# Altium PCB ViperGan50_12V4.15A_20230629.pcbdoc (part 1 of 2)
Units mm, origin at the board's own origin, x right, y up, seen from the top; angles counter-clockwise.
Board outline 450.19 x 402.29 mm, 2 copper layers (Top Layer, Bottom Layer); 71 components, 42 nets, 203 pads, 97 vias.
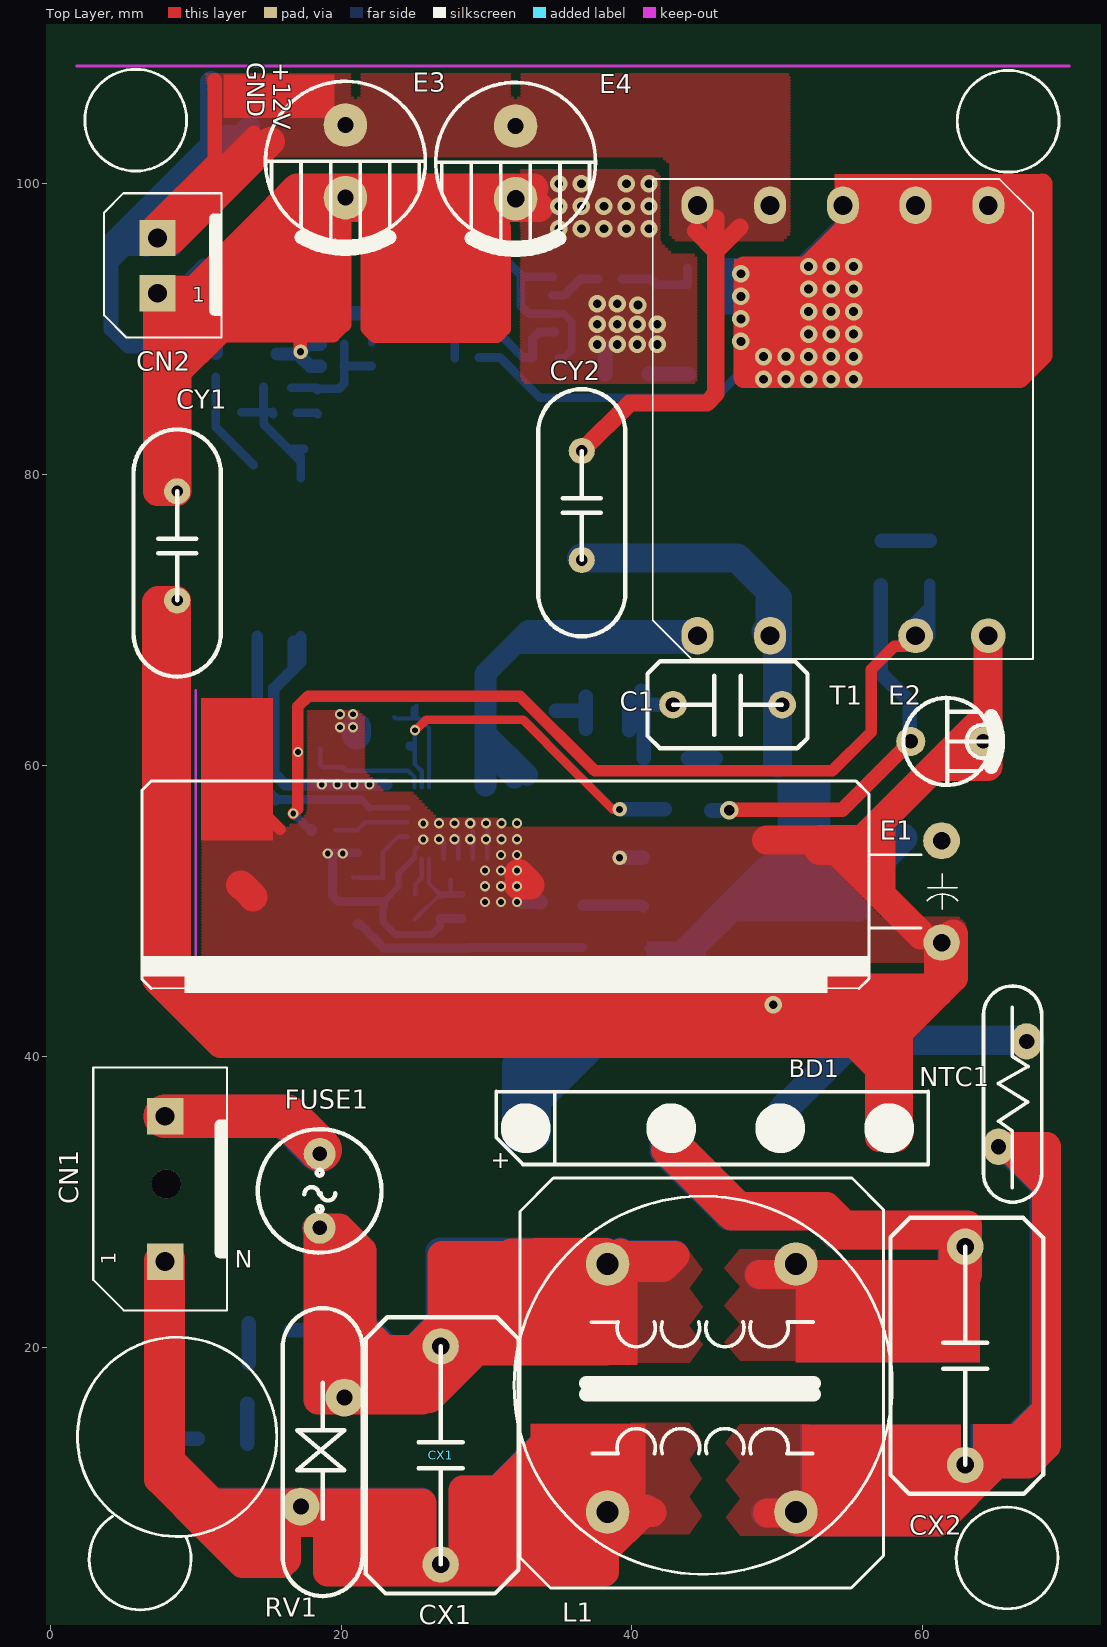
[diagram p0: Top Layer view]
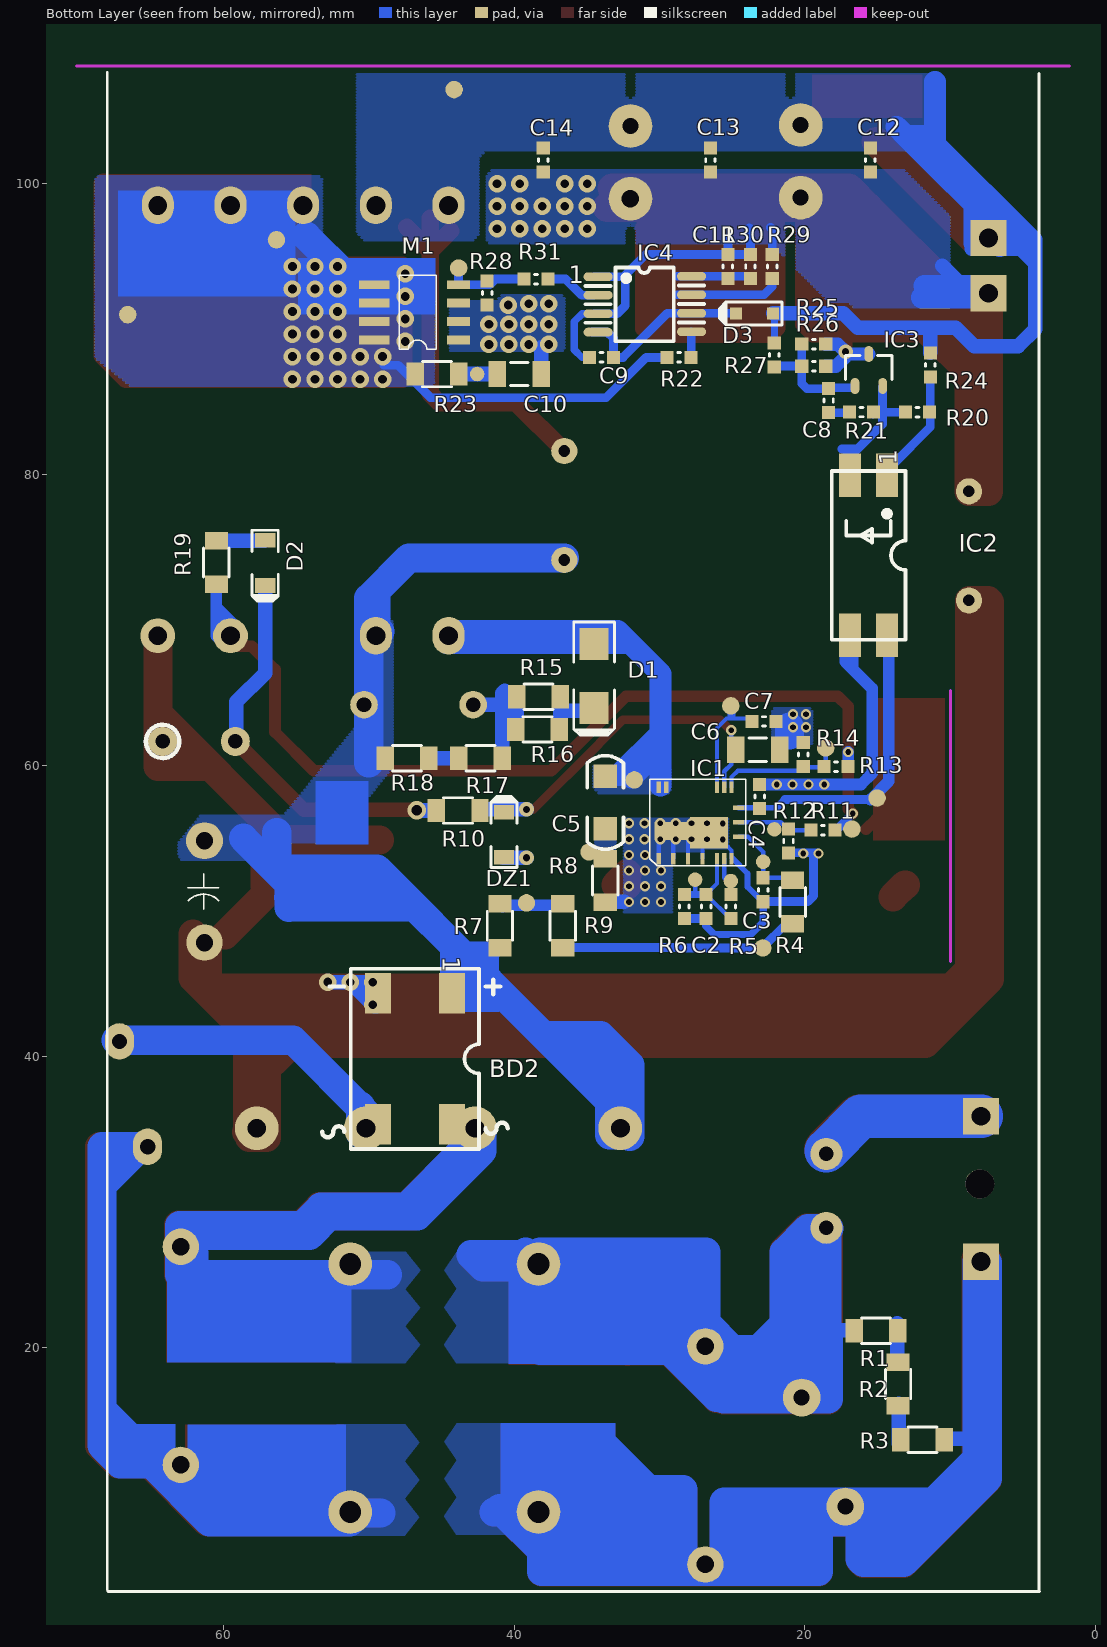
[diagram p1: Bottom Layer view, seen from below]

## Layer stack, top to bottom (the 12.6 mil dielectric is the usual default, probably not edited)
Top Solder: solder mask 0.0102, Solder Resist, Dk 3.5
Top Layer: signal copper 0.0356
Dielectric1: dielectric 0.32, FR-4, Dk 4.8
Bottom Layer: signal copper 0.0356
Bottom Solder: solder mask 0.0102, Solder Resist, Dk 3.5

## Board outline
-290.477,269.395 159.715,269.395 159.715,-132.89 159.009,-132.184 -290.477,-132.184

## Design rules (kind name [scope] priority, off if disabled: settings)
Clearance [All] p1: gap=0.2 ignorepadtopadclearanceinfootprint=FALSE except(0: Arc-Hole Track-Hole SMDPad-Hole THPad-Hole Via-Hole Fill-Hole Poly-Hole Region-Hole Text-Hole)
ComponentClearance [All] p1: gap=0 collisioncheckmode=3 verticalgap=0 showdistances=FALSE
FabricationTestPointUsage TestPointUsage [All] p1: valid=0 allowmultiple=FALSE
FabricationTestpoint Testpoint [(IsPad And (OnTopLayer Or OnBottomLayer))] p1: side=3 testpointundercomponent=TRUE minsize=1.016 maxsize=2.54 preferedsize=1.524 minholesize=0 maxholesize=1.016 preferedholesize=0.813 testpointgrid=0.025 allowsidetop=TRUE allowsidebottom=TRUE usegrid=TRUE gridtolerance=0
Height [All] p1: minheight=0 maxheight=32.4 prefheight=32.4
PlaneConnect [All] p1: planeconnectstyle=Direct reliefexpansion=0.508 reliefentries=4 reliefconductorwidth=0.254 reliefairgap=0.254
PolygonConnect [All] p1: connectstyle=Direct reliefconductorwidth=0.254 reliefentries=4 polygonreliefangle="90 Angle" airgapwidth=0.254
RoutingVias [All] p1: holewidth=0.711 width=1.27 viastyle="Through Hole" minholewidth=0.711 minwidth=1.27 maxholewidth=0.711 maxwidth=1.27
SilkToSolderMaskClearance SilkscreenOverComponentPads [IsPad] p1: minsilkscreentomaskgap=0.254 clearancetoexposedcopper=TRUE
SolderMaskExpansion [All] p1: expansion=0.102
Width [All] p1: maxlimit=4 minlimit=0.1 preferedwidth=0.254
24 further rules are at their usual default settings.

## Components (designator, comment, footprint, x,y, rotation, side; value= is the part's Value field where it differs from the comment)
BD1 "NC_16A 1000V" "2-D3-SB - 带散热片 - duplicate" 32.7,35.05 r0 top
BD2 "2A 1000V" "BD - SDIP - 4 - R" 46.825,39.825 r0 bottom locked (schematic designator BD1)
C1 "C806" "CAPF - 11.0*6.5*15.5 - 7.5B - 0.6 - L" 42.825,64.175 r0 top locked
C2 "10n" "CAPCC - 0603 - R" 26.797,50.301 r270 bottom (schematic designator C3)
C3 "220p" "CAPCC - 0603 - R" 22.875,51.45 r90 bottom (schematic designator C10)
C4 "470p" "CAPCC - 0603 - R" 23.114,57.861 r90 bottom (schematic designator C6)
C5 "NC-47p 630V 1206" 14-1206C-W 33.731,57.455 r270 bottom (schematic designator C12)
C6 "22u/35V 1206" 1206-C 23.35,61.025 r180 bottom (schematic designator C12)
C7 "105/25v" "CAPCC - 0603 - R" 22.825,63.025 r180 bottom (schematic designator C13)
C8 "105/25v" "CAPCC - 0603 - R" 18.377,85.09 r90 bottom (schematic designator C31)
C9 "2.2uf" "CAPCC - 0603 - R" 33.985,88.062 r180 bottom (schematic designator C8)
C10 "471 200V 1206" 1206-C 39.548,86.97 r0 bottom (schematic designator C2)
C11 "NC" "CAPCC - 0603 - R" 25.298,94.31 r90 bottom (schematic designator C8)
C12 "1nF" "CAPCC - 0603 - R" 15.5,101.625 r270 bottom (schematic designator C7)
C13 "0.1uF" "CAPCC - 0603 - R" 26.5,101.625 r270 bottom (schematic designator C7)
C14 "2.2uf" "CAPCC - 0603 - R" 38,101.625 r270 bottom (schematic designator C8)
CN1 "MKDS1.5/2- 5.08/ 3P" "CON - 2/5 - 2.5B - 0.6 - W - L" 9.725,25.875 r90 top
CN2 "MKDS-1/2-3.81 /2P" "CON - 4 - 2.5B - 0.7 - W - L" 9.35,90.7 r90 top locked (schematic designator CN6)
CX1 "0.47uF/275V" "CAPF - 17.5*8.5*14.5 - 15.0B - 0.6 - L" 26.85,5.05 r90 top
CX2 "0.47uF/275V" "CAPF - 17.5*8.5*14.5 - 15.0B - 0.6 - L" 62.925,11.9 r90 top
CY1 "C812" "CAPC - 17.0*6.0*20.0 - 7.5B - 0.6 - L"#1 8.725,78.85 r270 top
CY2 "C812" "CAPC - 17.0*6.0*20.0 - 7.5B - 0.6 - L"#2 36.55,81.625 r270 top
D1 "S1M" "DIODC - DO214AC - R" 34.5,66.15 r270 bottom
D2 "UFM17PL" "DIODC - SOD123 - R" 57.125,73.925 r270 bottom (schematic designator D23)
D3 "MMSD4148T1G" 4148-323 23.47,91.084 r0 bottom (schematic designator D41)
DZ1 "22V" "DIODC - SOD123 - R" 40.7,55.225 r90 bottom (schematic designator D23)
E1 "100uF-450V" C-AL-12.5*50-P5-L 46.975,51.35 r180 top locked
E2 "50V/22UF" "CAPE - Φ5*11 - 5.0T - 0.5 - L" 59.175,61.65 r0 top locked (schematic designator E3)
E3 "1500uF-25V-固态电容" E-5/10#1 20.295,101.549 r270 top locked
E4 "1500uF-25V-固态电容" E-5/10#2 32,101.473 r270 top locked (schematic designator E2)
FUSE1 "T3.15A/250V" "FUSE引线 - Φ8.5*8.0 - 5.08T - 0.6 - L" 18.525,28.2 r90 top (schematic designator FUSE2)
IC1 "Gan50" GAN50 30.048,53.594 r90 bottom locked
IC2 "EL1018" "IC - SMD - 4 - R" 15.625,74.45 r0 bottom
IC3 "4-IC(TL431)" "IC - SOT23 - R" 15.608,87.198 r270 bottom
IC4 "SRK1001" 4-SOIC-8 31.013,91.719 r180 bottom (schematic designator IC20)
L1 "SQ1515_30mH_卧" 卧式电感 44.875,17.35 r180 top locked
M1 "STL110N10F7" DFN5X6_1 46.634,91.161 r0 bottom locked (schematic designator D40)
NTC1 "2Ω-7.5B-0.8" NTC-B57237-S237 66.175,37.4 r270 top
R1 "470K-1206" "RESC - 1206 - R" 15.125,21.125 r180 bottom (schematic designator R23)
R2 "470K-1206" "RESC - 1206 - R" 13.6,17.45 r270 bottom (schematic designator R22)
R3 "470K-1206" "RESC - 1206 - R" 11.925,13.625 r180 bottom (schematic designator R21)
R4 "470k-1206" "RESC - 1206 - R" 20.85,50.6 r270 bottom (schematic designator R29)
R5 "100k" "RESC - 0603 - R" 25.095,50.301 r90 bottom (schematic designator R31)
R6 "24k" "RESC - 0603 - R" 28.296,50.301 r90 bottom (schematic designator R30)
R7 "4M7-1206" "RESC - 1206 - R" 40.975,48.975 r270 bottom (schematic designator R27)
R8 "NC_20R-1206" "RESC - 1206 - R" 33.731,52.095 r270 bottom (schematic designator R25)
R9 "4M7-1206" "RESC - 1206 - R" 36.65,48.975 r90 bottom (schematic designator R28)
R10 "100R-1206" "RESC - 1206 - R" 43.85,56.9 r180 bottom (schematic designator R12)
R11 "NC-680k" "RESC - 0603 - R" 18.771,55.55 r0 bottom (schematic designator R35)
R12 "0R" "RESC - 0603 - R" 21.133,54.813 r90 bottom (schematic designator R32)
R13 "220k" "RESC - 0603 - R" 17.856,59.919 r180 bottom (schematic designator R34)
R14 "36k" "RESC - 0603 - R" 20.117,60.757 r90 bottom (schematic designator R33)
R15 "20R-1206" "RESC - 1206 - R" 38.325,64.725 r0 bottom (schematic designator R16)
R16 "20R-1206" "RESC - 1206 - R" 38.4,62.475 r0 bottom (schematic designator R15)
R17 "150K-1206" "RESC - 1206 - R" 42.325,60.5 r0 bottom (schematic designator R14)
R18 "150K-1206" "RESC - 1206 - R" 47.375,60.5 r0 bottom (schematic designator R13)
R19 "20R-1206" "RESC - 1206 - R" 60.475,73.95 r270 bottom (schematic designator R31)
R20 "10k" "RESC - 0603 - R" 12.25,84.3 r0 bottom (schematic designator R44)
R21 "51k" "RESC - 0603 - R" 16.116,84.303 r180 bottom (schematic designator R45)
R22 "330R" "RESC - 0603 - R" 28.651,88.062 r180 bottom (schematic designator R50)
R23 "NC_20R-1206" "RESC - 1206 - R" 45.314,86.919 r180 bottom (schematic designator R8)
R24 "1k" "RESC - 0603 - R" 11.375,87.55 r270 bottom (schematic designator R43)
R25 "1.5M" "RESC - 0603 - R" 19.393,88.976 r180 bottom (schematic designator R51)
R26 "20k" "RESC - 0603 - R" 19.393,87.452 r180 bottom (schematic designator R42)
R27 "75k" "RESC - 0603 - R" 22.111,88.24 r270 bottom (schematic designator R41)
R28 "51k" "RESC - 0603 - R" 41.859,92.481 r90 bottom (schematic designator R46)
R29 "68k" "RESC - 0603 - R" 22.25,94.31 r270 bottom (schematic designator R49)
R30 "68k" "RESC - 0603 - R" 23.749,94.31 r90 bottom (schematic designator R48)
R31 "0R" "RESC - 0603 - R" 38.506,93.447 r180 bottom (schematic designator R47)
RV1 "TVR14561" "TVR - 19.5*5.5*26.0 - 8.08B - 0.8 - L(TVR14561)" 20.225,16.525 r270 top
T1 "POT3014骨架" ? 54.508,83.947 r270 top locked (schematic designator T3)

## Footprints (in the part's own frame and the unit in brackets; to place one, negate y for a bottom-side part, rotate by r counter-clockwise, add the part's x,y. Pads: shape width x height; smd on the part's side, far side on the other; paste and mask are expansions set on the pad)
"2-D3-SB - 带散热片 - duplicate" [mm]
  round 3 hole 1.3: 1(-0.001,-0.001) 2(10,-0.001) 3(17.5,-0.001) 4(25,-0.001)
  silkscreen extent -2.03,-2.5 27.69,2.54
4-SOIC-8 [mm]
  oval 2x0.6 smd: 1(-3.213,1.892) 2(-3.213,0.622) 3(-3.213,-0.648) 4(-3.213,-1.918) 5(3.213,-1.892) 6(3.213,-0.622) 7(3.213,0.648) 8(3.213,1.918)
  silkscreen extent -4.08,-2.55 4.07,2.53
14-1206C-W [mm]
  rect 1.6x1.6 smd: 1(-1.8,0) 2(1.8,0)
  silkscreen extent -3.22,-1.25 3.22,1.25
1206-C [mm]
  rect 1.2x1.8 smd: 1(-1.398,0.051) 2(1.602,0.051)
  silkscreen extent -0.5,-0.75 0.7,0.85, body extent -1.65,-0.85 1.85,0.95, height 1.45
4148-323 [mm]
  rect 0.8x0.8 smd: A(-1.275,0) K(1.275,0)
  silkscreen extent -1.9,-0.8 2.41,0.8, body extent -1.32,-0.65 1.33,0.65, height 1
"BD - SDIP - 4 - R" [mm]
  rect 1.8x2.8 smd: 1(-2.54,-4.5) 2(-2.54,4.5) 3(2.54,4.5) 4(2.54,-4.5)
  silkscreen extent -6.38,-6.2 6.38,6.2, body extent -4.14,-4.93 4.14,4.92, height 2.6
C-AL-12.5*50-P5-L [mm]
  round 2.54 hole 1.2: 1(-14.322,-3.471)
  round 2.5 hole 1.2: 2(-14.322,3.529)
  silkscreen extent -15.44,-7.59 40.77,6.68
"CAPC - 17.0*6.0*20.0 - 7.5B - 0.6 - L"#1 [mm]
  round 1.8 hole 0.8: 1(0,0) 2(7.5,0)
  silkscreen extent -4.25,-3 12.75,3, body extent -4.75,-3 12.25,3, height 20
"CAPC - 17.0*6.0*20.0 - 7.5B - 0.6 - L"#2 [mm]
  round 1.8 hole 0.8 mask+0.102: 1(0,0)
  round 1.8 hole 0.8: 2(7.5,0)
  silkscreen extent -4.25,-3 12.75,3, body extent -4.75,-3 12.25,3, height 20
"CAPCC - 0603 - R" [mm]
  rect 0.9x0.9 smd: 1(-0.825,0) 2(0.825,0)
  silkscreen extent -0.1,-0.33 0.1,0.32, body extent -0.85,-0.45 0.85,0.45, height 0.9
"CAPE - Φ5*11 - 5.0T - 0.5 - L" [mm]
  round 2 hole 1: 1(0,0) 2(5,0)
  silkscreen extent -0.5,-3 6.15,3
"CAPF - 11.0*6.5*15.5 - 7.5B - 0.6 - L" [mm]
  round 1.9 hole 1: 1(0,0) 2(7.5,0)
  silkscreen extent -1.75,-3 9.25,3
"CAPF - 17.5*8.5*14.5 - 15.0B - 0.6 - L" [mm]
  round 2.5 hole 1.2: 1(0,0) 2(15,0)
  silkscreen extent -2,-5.35 17,5.15, body extent -1.25,-4.25 16.25,4.25, height 14.5
"CON - 2/5 - 2.5B - 0.6 - W - L" [mm] "RAST2.5, 7251"
  rect 2.5x2.5 hole 1.3: 1(0,1.829) 2(10,1.829)
  silkscreen extent -3.35,-2.43 13.35,6.77, body extent -3.35,-2.43 13.35,6.77, height 15.5
"CON - 4 - 2.5B - 0.7 - W - L" [mm]
  rect 2.5x2.5 hole 1.3 mask-0.2: 1(1.775,1.975) 3(5.575,1.975)
  silkscreen extent -1.27,-2.43 8.65,5.65, body extent -3.35,-2.43 10.85,6.8, height 15.5
DFN5X6_1 [mm]
  rect 2.1x0.6 smd: D(3,-1.905) D(3,-0.635) D(3,0.635) D(3,1.905)
  rect 1.6x0.6 smd: G(-2.8,-1.905) S(-2.8,-0.635) S(-2.8,1.905) S(-2.8,0.635)
  silkscreen extent -1.27,-2.53 1.27,2.55
"DIODC - DO214AC - R" [mm]
  rect 2.2x2 smd: A(-2.2,0) K(2.2,0)
  silkscreen extent -3.72,-1.4 4.06,1.4, body extent -2.52,-1.45 2.52,1.45, height 2.44
"DIODC - SOD123 - R" [mm]
  rect 1x1.4 smd: A(-1.55,0) K(1.55,0)
  silkscreen extent -2.25,-0.9 2.64,0.9, body extent -1.82,-0.8 1.88,0.8, height 1.23
E-5/10#1 [mm]
  round 3 hole 1.1: 1(-2.5,0) 2(2.5,0)
  silkscreen extent -5.5,-5.5 6.01,5.5
E-5/10#2 [mm]
  round 3 hole 1.1: 1(-2.5,0)
  round 3 hole 1.2: 2(2.5,0)
  silkscreen extent -5.5,-5.5 6.01,5.5
"FUSE引线 - Φ8.5*8.0 - 5.08T - 0.6 - L" [mm]
  round 2.2 hole 1: 1(0,0) 2(5.08,0)
  silkscreen extent -1.71,-4.25 6.79,4.25, body extent -1.71,-4.25 6.79,4.25, height 9.02
GAN50 [mm]
  rect 0.8x0.3 smd: 1(0,0) 2(0,-1) 3(0,-2) 4(0,-3) 5(0,-4) 6(0,-4.5) 7(0,-5) 11(4.9,-5) 12(4.9,-4.5) 13(4.9,-4) 15(4.9,-0.5) 16(4.9,0)
  rect 0.3x0.8 smd: 8(1.5,-5.5) 9(2.5,-5.5) 10(3.5,-5.5)
  rect 2.15x2.6 smd: 17(1.778,-3.456)
  rect 1.22x2.6 smd: 17(1.905,-1.016)
  silkscreen extent -0.51,-5.97 5.46,0.64
"IC - SMD - 4 - R" [mm]
  rect 1.5x3 smd: 1(-1.27,-5.5) 2(1.27,-5.5) 3(1.27,5.5) 4(-1.27,5.5)
  silkscreen extent -2.54,-5.8 2.54,5.8
"IC - SOT23 - R" [mm]
  oval 1.1x0.6 smd: 1(1.1,-0.95) 2(-1.1,0) 3(1.1,0.95)
  silkscreen extent -1,-1.6 0.65,1.6, body extent -1.25,-1.5 1.25,1.5, height 1.09
NTC-B57237-S237 [mm]
  oval 2.5x2 hole 1.05: 1(-3.622,0.971) 2(3.622,-0.971)
  silkscreen extent -7.44,-1.99 7.44,2.01
"RESC - 0603 - R" [mm] "Chip Resistor, 2-Leads, Body 1.60x0.80mm, IPC Medium Density"
  rect 0.9x0.9 smd: 1(-0.825,0) 2(0.825,0)
  silkscreen extent -0.1,-0.33 0.1,0.32, body extent -0.8,-0.4 0.8,0.4, height 0.45
"RESC - 1206 - R" [mm] "Chip Resistor, 2-Leads, Body 3.10x1.58mm, IP"
  rect 1.2x1.6 smd: 1(-1.5,0) 2(1.5,0)
  silkscreen extent -1,-0.87 1,0.87, body extent -1.47,-0.73 1.48,0.72, height 0.55
"TVR - 19.5*5.5*26.0 - 8.08B - 0.8 - L(TVR14561)" [mm]
  round 2.6 hole 1.1: 1(0,0) 2(7.5,-3)
  silkscreen extent -6.15,-4.25 13.65,1.25, body extent -6,-4.25 13.5,1.25, height 26
卧式电感 [mm]
  round 3 hole 1.5: 1(6.549,8.69) 2(-6.403,8.69) 3(-6.403,-8.358) 4(6.549,-8.358)
  silkscreen extent -12.43,-14.27 12.57,13.92
? [mm]
  oval 2.6x2.2 hole 1.3: 2(-14.574,10) 2(-14.574,5) 3(-14.574,0) 4(-14.574,-5) 5(-14.574,-10) 6(15.026,-10) 7(15.026,-5)
  round 2.4 hole 1.3: 9(15.026,5) 10(15.026,10)
  silkscreen extent -16.38,-13.08 16.64,13.08

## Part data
BD1 BD2: library part 2-BD-1
C1 C2 C3 C4 C6 C7 C8 C9 C10 C11 C14: library part CAP-HX, "电?"
C5: library part CAP-HX
C12 C13 CY1 CY2: library part CAP
CN1: library part 11-CN2
CX1: library part C
CX2: library part C, "Capacit"
D1: library part D
D2 DZ1: library part DIODE
D3: library part 2-DIODE(二极管), "D"
E1 E3 E4: library part 14
IC2: library part OPTOISO2
IC3: library part T
IC4: library part SRK2001, "SRK2001"
M1: library part 0262704006, "STF16N65M5"
NTC1: library part NTC/PTC热敏
R1 R2 R3 R4 R7 R8 R9 R10 R15 R16 R17 R18 R19: library part 102J/0805
R5 R6 R11 R12 R13 R14: library part RES2
R20 R21 R22 R24 R25 R26 R27 R28 R29 R30 R31: library part RES1
R23: library part R-HX, "电阻"
T1: library part ER3591

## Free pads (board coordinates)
  round 2 hole 2: 0(7.975,31.225)
  round 1.2 smd far side: 11(15.039,57.759) 11(16.775,55.625) 11(18.575,61.2) 11(22.9,47.45) 11(25.1,64.1) 11(31.739,59.009) 11(34.85,54.05) 11(39.15,50.55) 26(43.815,94.209) 26(44.125,106.475) 26(56.35,96.15) 26(66.575,91)
  round 1 smd far side: 11(22.1,55.6) 11(22.875,53.375) 11(25.1,52.05) 11(27.55,52.15) 26(42.545,86.919)

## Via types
v1: diameter 1.2, hole 0.6, Top Layer to Bottom Layer, 55 vias
v2: diameter 0.7, hole 0.4, Top Layer to Bottom Layer, 38 vias
v3: diameter 1, hole 0.5, Top Layer to Bottom Layer, 3 vias
v4: diameter 1.27, hole 0.711, Top Layer to Bottom Layer, 1 vias

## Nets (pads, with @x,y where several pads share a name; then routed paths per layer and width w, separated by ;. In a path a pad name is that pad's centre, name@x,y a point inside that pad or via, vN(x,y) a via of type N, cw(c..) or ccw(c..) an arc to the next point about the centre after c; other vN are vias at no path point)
12V4A: C12.1 C13.1 C14.1 CN2.3 CY2.1 D3.A E3.1 E4.1 pad.26@44.125,106.475 R24.1 R27.1 T1.4 T1.5 | length 140.7
  Top Layer w1: CN2.3@6.875,96.475 6.875,97.25 11.325,101.7 11.325,107.117 ; CN2.3@6.95,96.475 14,103.525
  Top Layer w1.2: CY2.1@36.587,81.662 39.85,84.925 45.133,84.925 45.775,85.567 45.775,95.375 ; 44.375,96.775 45.775,95.375 ; 45.775,97.65 45.775,95.375 ; 47.4,97 45.775,95.375
  Top Layer w2: CN2.3@7.6,96.1 8.308,96.1 15.125,102.917
  Bottom Layer w0.5: D3.A@22.075,91.025 22.1,91 22.1,89.075 R27.1@22.111,89.065
  Bottom Layer w1: 7,98.225 6.6,97.825 4.175,95.4 ; CN2.3@7.8,96.1 6.6,96.1 5.725,96.1 5.163,95.538 ; CN2.3@8.513,95.538 5.163,95.538 ; R24.1@11.375,88.375 11.375,90.075 ; 11.4,103.4 11.063,103.062 4.175,96.175 4.175,95.4 ; D3.A@22.195,91.084 17.359,91.084 16.375,90.1 9.625,90.1 8.35,88.825 5.35,88.825 4.175,90 4.175,94.55 ; 4.175,94.55 5.163,95.538 ; 4.175,94.55 4.175,95.4
  Bottom Layer w1.5: CN2.3@6.6,95.7 6.6,96.1 6.6,97.825 6.6,98.1 11.063,102.562 ; CN2.3@7.375,96.275 7.375,97.6 8.337,98.562 ; CN2.3@8.337,95.913 8.337,98.562 ; 11.063,107.012 11.063,103.062 11.063,102.562 ; 13.7,103.925 13.063,103.287 ; 8.337,98.562 11.063,101.287 ; 11.063,101.287 11.063,102.562 ; 11.063,101.287 13.063,103.287 ; 11.063,102.562 11.787,103.287 13.063,103.287
AUX1: pad.11@16.775,55.625 R11.1 R13.2 R19.2 T1.9 | length 69
  Top Layer w0.8: v2(16.713,56.693) 17.025,57.005 v2(17.025,60.925) 17.025,64.05 17.745,64.77 32.305,64.77 37.45,59.625 53.775,59.625 56.45,62.3 56.45,66.6 58.05,68.2 T1.9@59.5,68.2 ; T1.9@59.053,68.453 T1.9@59.944,68.453
  Bottom Layer w0.6: v2(16.713,56.693) 17.856,55.55 R11.1@17.946,55.55
  Bottom Layer w0.8: R13.2@17.025,59.9 v2(17.025,60.925) ; R11.1@17.946,55.55 R11.1@17.958,55.562 ; T1.9@58.825,68.875 58.825,69.225 60.475,70.875 ; T1.9@59.5,68.925 59.5,68.912 T1.9@59.508,68.921 ; T1.9@60.025,68.45 60.475,68.9 60.475,70.875 ; R19.2@60.475,72.45 60.475,70.875
FB-VOUT: C4.1 IC1.10 IC2.4 pad.11@15.039,57.759 | length 21
  Bottom Layer w0.4: 21.946,57.094 IC1.10@24.548,57.094
  Bottom Layer w0.5: 21.382,57.658 21.946,57.094
  Bottom Layer w0.6: pad.11@15.492,57.658 21.382,57.658
  Bottom Layer w0.8: IC2.4@14.225,68.875 14.225,58.925 pad.11@15.492,57.658
GND2: C9.1 C10.1 C11.2 C12.2 C13.2 C14.2 CN2.1 CY1.1 E3.2 E4.2 IC3.2 IC4.1 IC4.3 M1.S R25.2 R26.2 R28.1 R29.1 R30.2 | length 227.7
  Top Layer w0.92: v3@17.184,88.418 17.184,89.6 17.184,90.625 17.184,91.869 17.184,92.759
  Top Layer w1: CN2.1@6.825,92.45 8.725,90.55 9.675,89.6 11.225,89.6 17.184,89.6 19.475,89.6 20.2,90.325 20.2,98.387 E3.2@20.2,98.55 ; 21.825,96.517 21.825,90.075 22.35,89.55 30.7,89.55 31.2,90.05 31.2,97.025
  Top Layer w2: CN2.1@7.225,92.675 9.925,92.675 15.637,98.387 ; CN2.1@7.375,91.575 7.375,78.85 CY1.1@8.725,78.85 8.725,87.1 ; CN2.1@8.45,91.575 8.725,91.575 ; 8.725,91.925 8.725,91.575 ; 9.45,90.625 11.313,90.625 ; 12.35,90.725 12.25,90.625 ; 19.206,94.544 15.231,94.544 ; 19.344,96.769 17.456,96.769 ; 19.456,95.869 16.556,95.869 ; 19.494,93.106 13.794,93.106 ; 19.519,91.869 17.184,91.869 12.556,91.869 ; 19.625,90.625 17.184,90.625 12.25,90.625 ; E4.2@33.275,99.717 16.967,99.717 15.637,98.387 ; 33.613,98.387 20.2,98.387 E3.2@19.075,98.387 ; 8.725,87.1 8.725,90.55 8.725,91.575 ; 8.725,87.1 11.225,89.6 12.25,90.625 ; 8.725,91.575 10.688,91.575 17.5,98.387 ; 11.313,90.625 12.556,91.869 ; 11.313,90.625 12.25,90.625 ; 12.556,91.869 13.794,93.106 ; 13.794,93.106 15.231,94.544 ; 15.231,94.544 16.556,95.869 ; 15.637,98.387 17.5,98.387 ; 16.556,95.869 17.456,96.769 ; 17.456,96.769 E3.2@19.075,98.387 ; 17.5,98.387 E3.2@19.075,98.387
  Bottom Layer w0.5: IC4.3@34.227,91.072 IC4.3@34.246,91.091 ; IC4.3@34.531,91.072 35.319,91.072 35.865,90.526 35.865,88.595 35.331,88.062 C9.1@34.935,88.062
  Bottom Layer w0.6: R29.1@22.25,95.059 R29.1@22.25,95.135 22.25,96.876 22.377,97.003 ; R30.2@23.749,95.059 R30.2@23.749,95.135 ; 23.825,96.977 23.749,96.901 R30.2@23.749,95.135 ; C11.2@25.298,95.059 C11.2@25.298,95.135 ; 25.298,96.317 C11.2@25.298,95.135 ; IC4.3@34.531,91.072 IC4.3@34.227,91.072 32.906,91.072 32.36,91.618 32.36,93.726 ; IC4.1@34.531,93.612 IC4.1@34.227,93.612 32.474,93.612 32.36,93.726 ; R30.2@23.749,95.135 C11.2@25.298,95.135 ; C11.2@25.298,95.135 30.95,95.135 32.36,93.726
  Bottom Layer w0.92: IC3.2@15.608,88.298 v3@17.064,88.298 ; R26.2@18.568,87.452 17.869,87.452 17.209,88.113 v3(17.209,88.443) 17.742,88.976 R25.2@18.568,88.976
  Bottom Layer w1: 9.275,93.1 10.55,94.375 ; C10.1@38.149,86.919 38.151,86.92 v1@38.151,88.773
  Bottom Layer w1.5: CN2.1@7.338,92.988 11.787,92.988 ; CN2.1@7.513,92.187 11.963,92.187
  other v1: 37.617,88.951 38.989,88.951 40.361,88.951 41.732,88.951 37.617,90.348 38.989,90.348 40.361,90.348 41.732,90.348 40.411,91.663 37.617,91.745 38.989,91.745 34.976,96.901 36.525,96.901 38.075,96.901 39.624,96.901 41.173,96.901 34.976,98.45 36.525,98.45 38.075,98.45 39.624,98.45 41.173,98.45 34.976,100 36.525,100 39.624,100 41.173,100
L: CN1.2 FUSE1.2 | length 23.2
  Top Layer w3: CN1.2@7.896,35.875 16.275,35.875 FUSE1.2@18.575,33.575
  Bottom Layer w3: CN1.2@7.896,35.875 16.15,35.875 FUSE1.2@18.525,33.5
MOS: C5.1 D1.A IC1.15 IC1.16 pad.11@31.739,59.009 T1.6 | length 43.3
  Bottom Layer w1.5: IC1.16@29.925,58.6 29.925,61.175 ; pad.11@31.925,59.175 29.925,61.175 ; 32.8,59.35 29.925,62.225 ; T1.6@44.508,68.732 T1.6@44.508,68.921 44.179,69.25 32.875,69.25 32.05,68.425 ; T1.6@44.625,68.425 32.05,68.425 ; 29.925,61.175 29.925,62.225 ; 29.925,62.225 29.925,66.3 32.05,68.425
N: CN1.1 CX1.1 L1.1 R3.2 RV1.2 | length 386.5
  Top Layer w2: CN1.1@7.45,25.975 7.45,10.9 11.013,7.338 ; CN1.1@8.25,26.1 8.25,12.2 11.175,9.275 RV1.2@16.225,9.275 ; 13.6,5.375 16.225,5.375 ; 14.775,7.925 16.225,7.925 ; 15.787,7.338 11.013,7.338 ; 19.25,8.775 19.075,8.95 19.075,7.925 ; 19.275,6.375 25.575,6.375 ; 25.575,5 25.575,6.375 ; 28.863,7.663 35.763,7.663 ; 29.3,9.225 37.325,9.225 35.763,7.663 ; 30.625,10 30.775,10.15 ; 34.175,6.5 28.375,6.5 ; 34.187,13.563 30.775,10.15 ; 36.25,9.4 L1.1@38.1,9.4 ; 36.425,8.05 L1.1@38.1,8.05 ; 37.425,5.275 38.1,5.95 ; L1.1@37.8,7.55 34.775,4.525 ; L1.1@38.326,8.61 40.76,8.61 ; 39.9,9.4 L1.1@38.1,9.4 ; 40.075,8.05 L1.1@38.1,8.05 ; 40.987,8.837 40.76,8.61 ; 41.385,8.61 40.76,8.61 ; 11.013,7.338 13.225,5.125 15.975,5.125 16.225,5.375 ; 16.225,5.375 16.225,7.925 ; 16.225,7.925 RV1.2@16.225,9.275 ; 16.225,7.925 19.075,7.925 ; RV1.2@16.225,9.275 25.575,9.275 25.575,7.925 ; 19.075,7.925 19.075,4.525 34.775,4.525 ; 19.075,7.925 25.575,7.925 ; 25.575,6.375 25.575,7.925 ; 28.375,6.5 28.375,4.975 33.075,4.975 35.763,7.663 ; 28.375,6.5 28.375,10.15 30.775,10.15 ; 30.775,10.15 38.1,10.15 L1.1@38.1,9.4 ; 34.775,4.525 38.1,4.525 38.1,5.95 ; 38.1,5.95 40.76,8.61 ; 38.1,5.95 L1.1@38.1,8.05 ; L1.1@38.1,8.05 L1.1@38.1,9.4
  Bottom Layer w1: 7.403,13.681 7.45,13.681 8.15,13.681 R3.2@10.146,13.681
  Bottom Layer w2: CN1.1@7.45,25.8 7.45,13.681 7.45,12.1 ; 8.15,12.35 11.175,9.325 RV1.2@16.225,9.325 ; CN1.1@8.15,25.925 8.15,13.681 8.15,12.8 7.45,12.1 ; 13.6,5.425 16.225,5.425 ; 14.775,7.975 16.225,7.975 ; 15.787,7.388 11.013,7.388 ; 19.25,8.825 19.075,9 19.075,7.975 ; 19.275,6.425 25.575,6.425 ; 25.575,5.05 25.575,6.425 ; 28.863,7.713 35.763,7.713 ; 29.3,9.275 37.325,9.275 35.763,7.713 ; 30.625,10.05 30.775,10.2 ; 34.175,6.55 28.375,6.55 ; 34.187,13.613 30.775,10.2 ; 36.25,9.45 L1.1@38.1,9.45 ; 36.425,8.1 L1.1@38.1,8.1 ; 37.425,5.325 38.1,6 ; L1.1@37.8,7.6 34.775,4.575 ; L1.1@38.326,8.66 40.76,8.66 ; 39.9,9.45 L1.1@38.1,9.45 ; 40.075,8.1 L1.1@38.1,8.1 ; 40.987,8.887 40.76,8.66 ; 41.385,8.66 40.76,8.66 ; 7.45,12.1 7.45,10.95 11.013,7.388 ; 11.013,7.388 13.225,5.175 15.975,5.175 16.225,5.425 ; 16.225,5.425 16.225,7.975 ; 16.225,7.975 19.075,7.975 ; 16.225,7.975 RV1.2@16.225,9.325 ; RV1.2@16.225,9.325 25.575,9.325 25.575,7.975 ; 19.075,7.975 25.575,7.975 ; 19.075,7.975 19.075,4.575 34.775,4.575 ; 25.575,6.425 25.575,7.975 ; 28.375,6.55 28.375,5.025 33.075,5.025 35.763,7.713 ; 28.375,6.55 28.375,10.2 30.775,10.2 ; 30.775,10.2 38.1,10.2 L1.1@38.1,9.45 ; 34.775,4.575 38.1,4.575 38.1,6 ; 38.1,6 40.76,8.66 ; 38.1,6 L1.1@38.1,8.1 ; L1.1@38.1,8.1 L1.1@38.1,9.45
NetBD1_2: BD1.2 BD2.2 CX2.2 L1.3 | length 134.6
  Top Layer w2: 42.3,33.55 46.85,29 52.85,29 54.15,27.7 62.225,27.7 CX2.2@63,26.925 ; BD1.2@43.05,34 47.4,29.65 53.375,29.65 54.65,28.375 63.075,28.375 CX2.2@63.075,26.925 ; 48.775,25 63.075,25 CX2.2@63.075,26.65 ; 62.1,22.825 CX2.2@62.1,26.475
  Bottom Layer w2: BD1.2@42.2,35.05 42.2,33.475 46.65,29.025 52.725,29.025 54.075,27.675 62.15,27.675 CX2.2@62.925,26.9 ; 43.5,33.55 47.425,29.625 53.3,29.625 54.575,28.35 63,28.35 CX2.2@63,26.9 ; 48.7,24.975 63,24.975 CX2.2@63,26.625 ; 62.025,22.8 CX2.2@62.025,26.45
NetBD1_3: BD1.3 BD2.3 NTC1.1 | length 22.5
  Bottom Layer w2: BD2.3@50.25,34.7 50.25,36.15 55.2,41.1 NTC1.1@67.375,41.1 ; BD1.3@50.575,34.7 50.575,36.575
NetC1_1: C1.1 R15.2 R16.2 R17.1 | length 9
  Bottom Layer w1: R16.2@39.825,62.425 R15.2@39.825,64.725 ; 40.65,65.15 40.825,64.975 40.825,64.175 ; R17.1@40.825,60.5 40.825,64.175 ; C1.1@42.825,64.175 40.825,64.175
NetC2_1: C2.1 IC1.5 pad.11@27.55,52.15 R5.1 R6.2 | length 7.8
  Bottom Layer w0.3: R5.1@25.051,49.38 C2.1@26.797,51.126 ; IC1.5@26.048,53.594 26.048,51.877 C2.1@26.825,51.1 ; 27.55,51.15 pad.11@27.55,52.15
  Bottom Layer w0.5: C2.1@26.825,51.075 26.876,51.126 R6.2@28.296,51.126
NetC3_2: C3.2 IC1.8 pad.11@22.875,53.375 R4.1 | length 5.6
  Bottom Layer w0.3: R4.1@20.825,52.325 R4.1@20.865,52.285 ; R4.1@21.115,52.285 C3.2@22.758,52.285 ; C3.2@22.875,52.225 C3.2@22.875,52.275 22.875,54.05 23.919,55.094 IC1.8@24.548,55.094
NetC5_2: C5.2 pad.11@34.85,54.05 R8.1
NetC7_1: C7.1 IC1.13 pad.11@25.1,64.1 | length 8.4
  Bottom Layer w0.3: C7.1@23.66,63.322 23.757,63.225 24.925,63.225 ; pad.11@24.925,63.925 24.925,63.225 ; pad.11@25.175,64.125 25.175,63.225 ; IC1.13@26.048,58.494 26.048,62.577 25.4,63.225 25.175,63.225 ; 24.925,63.225 25.175,63.225
NetC8_1: C8.1 R21.1 | length 1.4
  Bottom Layer w0.6: R21.1@16.941,84.258 C8.1@18.32,84.258 ; C8.1@18.37,84.157 C8.1@18.377,84.163
NetC8_2: C8.2 IC3.1 R25.1 R26.1 R27.2 | length 8.4
  Bottom Layer w0.6: IC3.1@16.584,85.968 C8.2@18.324,85.968 ; C8.2@18.324,85.867 C8.2@18.377,85.813 ; C8.2@18.377,85.915 19.862,85.915 20.218,86.271 R26.1@20.218,87.452 R25.1@20.218,88.976 ; R26.1@20.18,87.478 R27.2@22.111,87.478
NetC9_2: C9.2 D3.K IC4.4 IC4.6 | length 12.5
  Bottom Layer w0.6: D3.K@24.745,91.097 28.791,91.097 29.477,91.097 32.512,88.062 C9.2@33.035,88.062 ; C9.2@33.16,88.062 33.16,89.37 33.591,89.802 IC4.4@34.671,89.802
NetC10_2: C10.2 pad.26@42.545,86.919 R23.2 | length 2.8
  Bottom Layer w1: C10.2@41.149,86.919 pad.26@42.545,86.919 R23.2@43.915,86.919
NetC11_1: C11.1 IC4.8 R30.1 | length 5.1
  Bottom Layer w0.6: R30.1@23.749,93.485 23.901,93.637 25.298,93.637 IC4.8@27.8,93.637 IC4.8@28.791,93.637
